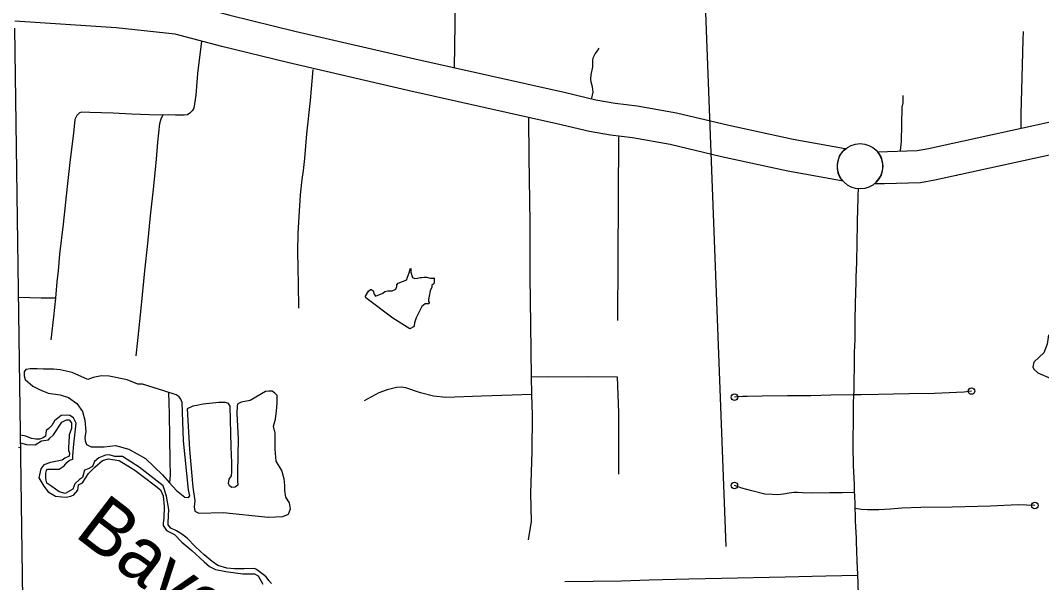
# Model space of a CAD drawing. Extents: x 1127717 to 1741049, y 2026793 to 2244711.
# Drawn here: x 1289221 to 1297097, y 2102398 to 2106736 of the extents above; entities that cross this region are included whole.
import ezdxf

# ---------------------------------------------------------------- set-up
doc = ezdxf.new("R2010")
doc.units = 0
for name, color, linetype in [('10', 7, 'Continuous'), ('2', 7, 'Continuous'), ('24', 7, 'Continuous'), ('31', 7, 'Continuous'), ('35', 7, 'Continuous'), ('5', 7, 'Continuous')]:
    doc.layers.add(name, color=color, linetype=linetype)

msp = doc.modelspace()

# ---------------------------------------------------------------- linework, layer by layer
at = {"layer": '10'}
for points in [[(1289179.3, 2106980.8), (1289979, 2106928.2), (1290461.1, 2106877.2), (1290836.1, 2106777), (1291337.3, 2106654.2)], [(1291279.5, 2106411), (1290774, 2106534.8), (1290415.4, 2106630.7), (1289960.3, 2106678.8), (1289177.8, 2106730.6)], [(1291337.3, 2106654.2), (1292263.9, 2106440), (1293413.8, 2106182.9), (1293659.5, 2106123.9), (1293808.1, 2106097.8), (1293978.4, 2106076.8), (1294281.4, 2106024.4), (1294684.5, 2105928.6), (1295180.4, 2105820.3), (1295582.2, 2105748.2)], [(1295558.2, 2105498.5), (1295552.6, 2105499.1), (1295140.4, 2105573.1), (1294628.9, 2105684.9), (1294231.2, 2105779.4), (1293941.8, 2105829.5), (1293771.2, 2105850.4), (1293608.6, 2105879), (1293357.3, 2105939.4), (1292208.5, 2106196.2), (1291279.5, 2106411)], [(1295830.9, 2105723.6), (1296135.9, 2105732.8), (1296223.9, 2105748.7), (1297326.3, 2105989.4), (1297777.1, 2106096.7), (1297925, 2106120.5), (1298884, 2106193.6), (1299004.5, 2106199.4), (1299783, 2106134), (1299881.1, 2106117.4), (1301117.7, 2105747.5)], [(1301415.4, 2105356.5), (1301034.6, 2105511.4), (1299824.2, 2105873.5), (1299751.6, 2105885.8), (1299000, 2105948.9), (1298901.1, 2105944.1), (1297954.4, 2105872), (1297825.9, 2105851.4), (1297381.9, 2105745.7), (1296272.8, 2105503.5), (1296162.1, 2105483.4), (1295884.9, 2105475.1), (1295807.6, 2105475.7)], [(1296442.2, 2105540.5), (1296413.7, 2105534.3)]]:
    msp.add_lwpolyline(points, dxfattribs=at)
for centre, radius, start, end in [((1295700.7, 2105610.8), 181.4, 130.79211, 218.24709), ((1295696.9, 2105611.2), 175, 309.25532, 39.99123)]:
    msp.add_arc(centre, radius, start, end, dxfattribs=at)
at = {"layer": '2'}
msp.add_lwpolyline([(1289248.7, 2101537.9), (1289178.5, 2106676.9)], dxfattribs=at)
at = {"layer": '24'}
msp.add_circle((1295696.9, 2105611.2), 175, dxfattribs=at)
at = {"layer": '31'}
for points in [[(1292567.4, 2106372.2), (1292578.5, 2107043.3), (1292584.3, 2107396.4), (1292585.4, 2107433.3)], [(1296939.3, 2105904.9), (1296939.3, 2106019.2), (1296946.9, 2106292.8), (1296954.5, 2106589.2), (1296957.5, 2106650)], [(1290616.7, 2106576.9), (1290587.1, 2106326.4), (1290574, 2106159.9), (1290557.7, 2106058.7), (1290546.3, 2106037.5), (1290528.4, 2106019.5), (1290508.8, 2106008.1), (1290482.7, 2106004.8), (1290415.8, 2106006.5), (1290362, 2106008.1), (1290317.9, 2106006.5), (1290215.1, 2106008.1), (1290078.1, 2106013), (1289936.1, 2106019.5), (1289756.7, 2106026.1), (1289694.7, 2106029.3), (1289676.7, 2106022.8), (1289655.5, 2106001.6), (1289640.9, 2105970.6), (1289629.4, 2105865.5), (1289603.3, 2105663.1), (1289580.5, 2105454.2), (1289549.5, 2105163.7), (1289521.8, 2104932), (1289512, 2104803.3), (1289502.2, 2104718.5), (1289490.8, 2104592.8)], [(1293627.7, 2106137.7), (1293638.6, 2106182.5), (1293633.9, 2106223.4), (1293622.5, 2106260.4), (1293619.6, 2106283.2), (1293623.4, 2106316.5), (1293634.8, 2106377.3), (1293634.8, 2106406.7), (1293634.8, 2106432.4), (1293640.5, 2106452.3), (1293652.9, 2106478), (1293670.9, 2106502.7), (1293684.2, 2106522.6)], [(1291475.6, 2106356.9), (1291454.5, 2106118.6), (1291426.8, 2105860.7), (1291410.5, 2105669.7), (1291400.7, 2105578.3), (1291390.9, 2105508.2), (1291379.5, 2105390.7), (1291368.1, 2105224.2), (1291361.5, 2105092), (1291358.3, 2104955.9), (1291361.5, 2104823.7), (1291363.2, 2104701.3), (1291364.8, 2104516.9)], [(1296009.2, 2105731.7), (1296016.7, 2105802.9), (1296020.5, 2106067), (1296028.1, 2106101.2), (1296028.1, 2106156.3)], [(1290112.8, 2104148.2), (1290126, 2104266), (1290155.1, 2104538.5), (1290181.5, 2104803.2), (1290202.7, 2105014.1), (1290223.9, 2105228.4), (1290250.3, 2105458.6), (1290270.1, 2105665.6), (1290279.4, 2105797.9), (1290296.6, 2105940.8), (1290305.9, 2105976.5), (1290317.9, 2106006.5)], [(1293140, 2102728.1), (1293163.3, 2102870.1), (1293158.4, 2103089.3), (1293166.6, 2103409.9), (1293169.9, 2103691.3), (1293165, 2103849.9), (1293163.3, 2103989), (1293158.4, 2104386.9), (1293151.9, 2104761.5), (1293153.5, 2105176.1), (1293145.6, 2105680), (1293140.8, 2105987.8)], [(1293834.7, 2105839.3), (1293825.6, 2104422)], [(1295679, 2102454), (1295678.5, 2102478.2), (1295677.2, 2102496.4), (1295676.2, 2102522.1), (1295675.3, 2102551.4), (1295674.3, 2102584), (1295672.7, 2102619.3), (1295671.1, 2102657.6), (1295669.9, 2102698.5), (1295668.1, 2102741.1), (1295666.8, 2102784.8), (1295664.3, 2102829.6), (1295662.4, 2102874.4), (1295660.6, 2102920.2), (1295658.9, 2102966.6), (1295657.9, 2103013.6), (1295656.3, 2103060.5), (1295654.6, 2103107.9), (1295652.5, 2103155.9), (1295650.6, 2103204.7), (1295648.6, 2103253.7), (1295646.8, 2103303.2), (1295645, 2103352.6), (1295643, 2103402), (1295642.5, 2103451.8), (1295642.7, 2103501.6), (1295643.5, 2103550.2), (1295644.7, 2103598.2), (1295645.8, 2103645.8), (1295645.3, 2103692.8), (1295646, 2103740.7), (1295647, 2103789), (1295648.6, 2103837.6), (1295650, 2103886.7), (1295650.9, 2103935.8), (1295652, 2103984.3), (1295653.4, 2104032.5), (1295654, 2104080.1), (1295654.3, 2104127.6), (1295654.9, 2104175.5), (1295656.1, 2104224), (1295658, 2104273.7), (1295657.9, 2104324), (1295658.7, 2104376.7), (1295660, 2104430.2), (1295664, 2104649.1), (1295665.4, 2104703.9), (1295667.1, 2104758.6), (1295668.6, 2104813), (1295670.5, 2104866.8), (1295672.3, 2104919.8), (1295673.1, 2104971.7), (1295674, 2105022.2), (1295674.7, 2105071.3), (1295675.6, 2105119.1), (1295676.4, 2105165), (1295677.4, 2105210.5), (1295678.4, 2105255.1), (1295679.5, 2105299.6), (1295681.3, 2105343.3), (1295682.7, 2105385.6), (1295684.4, 2105436.6)], [(1289490.8, 2104592.8), (1289379.8, 2104594.4), (1289206.9, 2104597.8)], [(1289490.8, 2104592.8), (1289475.3, 2104448.6), (1289455.4, 2104271.3)], [(1297151.2, 2104310.2), (1297140.5, 2104237.9), (1297113.5, 2104170.4), (1297077.4, 2104138.8), (1297036.9, 2104098.3), (1297027.9, 2104062.3), (1297036.9, 2104044.2), (1297068.4, 2104017.2), (1297163, 2103976.7), (1297203.5, 2103954.1), (1297208, 2103936.1), (1297208, 2103855), (1297199, 2103512.7)], [(1293163.3, 2103989), (1293292.5, 2103986.2), (1293596.7, 2103989.5), (1293824.2, 2103985.7)], [(1293824.2, 2103985.7), (1293834.4, 2103707.8), (1293834.4, 2103585.5), (1293834.4, 2103419), (1293832.7, 2103305.1), (1293834.4, 2103235.5)], [(1293165, 2103849.9), (1293014.5, 2103843.9), (1292775.8, 2103835.7), (1292501.1, 2103827.5), (1292406.3, 2103835.7), (1292306.5, 2103863.5), (1292193.7, 2103901.1), (1292156.1, 2103906), (1292120.1, 2103904.4), (1292048.2, 2103886.4), (1291984.4, 2103861.9), (1291871.6, 2103799.7)], [(1296556.2, 2103876.4), (1296497.3, 2103866.9), (1296271.3, 2103857.4), (1296073.8, 2103855.5), (1295836.4, 2103849.8), (1295705.3, 2103846), (1295648.8, 2103846)], [(1295648.8, 2103846), (1295472.3, 2103844.1), (1295316.5, 2103838.4), (1295138, 2103838.4), (1294940.5, 2103836.5), (1294824.6, 2103834.6), (1294790.4, 2103834.6), (1294727.8, 2103828.9)], [(1295655.1, 2103093.7), (1295558, 2103090.3), (1295459.9, 2103090.3), (1295322.5, 2103088.6), (1295252.2, 2103090.3), (1295213, 2103093.6), (1295185.2, 2103093.6), (1295150.8, 2103088.6), (1295105, 2103080.5), (1295059.3, 2103075.6), (1295020, 2103077.2), (1294962.8, 2103080.5), (1294863, 2103106.6), (1294784.6, 2103127.9), (1294727.3, 2103147.5)], [(1297044.3, 2102992.9), (1296917.1, 2102998.6), (1296702.4, 2102989.1), (1296408.1, 2102981.5), (1296164.9, 2102977.7), (1296018.7, 2102973.9), (1295931.3, 2102964.4), (1295840.2, 2102960.6), (1295754.7, 2102958.7), (1295707.2, 2102962.5), (1295658.8, 2102970.1)], [(1295679, 2102454), (1295432.1, 2102449.1), (1295119.8, 2102440.9), (1294627.6, 2102431.1), (1294375.8, 2102424.5), (1294070, 2102416.4), (1293857.4, 2102409.8), (1293418.4, 2102403.3)], [(1295958, 2101269.5), (1295927.5, 2101281.2), (1295898.4, 2101296.3), (1295872, 2101316.7), (1295848.5, 2101341.2), (1295827.5, 2101368.1), (1295807.8, 2101396.6), (1295788, 2101425.1), (1295768, 2101454.4), (1295748.6, 2101484.4), (1295730.7, 2101513.7), (1295707.5, 2101571.2), (1295704, 2101598.1), (1295704.4, 2101624.3), (1295695.3, 2101937.1), (1295690.4, 2102084.3), (1295685.5, 2102293.7), (1295682.2, 2102398.4), (1295679, 2102454)]]:
    msp.add_lwpolyline(points, dxfattribs=at)
for centre in [(1296556.2, 2103876.4), (1294727.8, 2103828.9), (1294727.3, 2103147.5), (1297044.3, 2102992.9)]:
    msp.add_circle(centre, 25, dxfattribs=at)
at = {"layer": '35'}
for points in [[(1291884.7, 2104595), (1291881.4, 2104608.1), (1291905.9, 2104647.4), (1291920.6, 2104660.4), (1291928.8, 2104660.4), (1291940.2, 2104650.6), (1291950.1, 2104624.5), (1291958.2, 2104609.7), (1291972.9, 2104613), (1292017.1, 2104631), (1292030.2, 2104645.7), (1292054.7, 2104649), (1292087.4, 2104649), (1292115.2, 2104662.1), (1292123.4, 2104683.3), (1292125, 2104696.4), (1292134.8, 2104707.9), (1292167.5, 2104721), (1292200.2, 2104734.1), (1292203.5, 2104747.1), (1292221.5, 2104796.2), (1292228, 2104819.1), (1292232.9, 2104822.4), (1292232.9, 2104794.6), (1292244.4, 2104753.7), (1292262.4, 2104745.5), (1292283.6, 2104747.1), (1292304.9, 2104753.7), (1292316.3, 2104753.7), (1292335.9, 2104755.3), (1292352.3, 2104755.3), (1292381.7, 2104748.8), (1292407.9, 2104748.8), (1292412.8, 2104750.4), (1292411.2, 2104729.1), (1292411.2, 2104712.8), (1292409.5, 2104703), (1292394.8, 2104693.2), (1292393.2, 2104678.4), (1292380.1, 2104650.6), (1292373.6, 2104609.7), (1292368.6, 2104583.6), (1292368.6, 2104567.2), (1292375.2, 2104554.1), (1292367, 2104549.2), (1292342.5, 2104549.2), (1292316.3, 2104529.6), (1292316.3, 2104527.9), (1292272.2, 2104441.3), (1292260.7, 2104403.6), (1292257.5, 2104380.7), (1292252.6, 2104372.6), (1292223.1, 2104356.2)], [(1292223.1, 2104356.2), (1292093.9, 2104439.6), (1291884.7, 2104595)], [(1290325.8, 2103877.4), (1290162.1, 2103930.3), (1290126.8, 2103930.3), (1290043.6, 2103963.1), (1289905.1, 2103990.8), (1289847.1, 2103993.3), (1289781.6, 2103980.7), (1289741.3, 2103965.6), (1289620.4, 2104018.5), (1289527.2, 2104041.2), (1289476.8, 2104046.2), (1289398.7, 2104046.2), (1289350.8, 2104048.8), (1289295.4, 2104048.8), (1289262.6, 2104043.7), (1289250, 2104023.6), (1289250, 2103993.3), (1289257.6, 2103965.6), (1289315.5, 2103915.2), (1289368.4, 2103887.5), (1289433.9, 2103859.7), (1289527.2, 2103847.1), (1289592.7, 2103827), (1289655.6, 2103781.6), (1289698.5, 2103718.6), (1289718.6, 2103650.5), (1289726.2, 2103564.9), (1289718.6, 2103514.5), (1289721.2, 2103491.8), (1289731.2, 2103464), (1289766.5, 2103446.4), (1289867.3, 2103446.4), (1289952.9, 2103456.5), (1290056.2, 2103428.8), (1290184.7, 2103355.7), (1290315.7, 2103229.7), (1290371.2, 2103169.2), (1290424.1, 2103108.7), (1290489.6, 2103058.3), (1290517.3, 2103055.8), (1290527.4, 2103068.4), (1290517.3, 2103113.7), (1290479.5, 2103491.8), (1290469.4, 2103789.2), (1290456.8, 2103814.4), (1290444.2, 2103832), (1290421.6, 2103847.1)], [(1290421.6, 2103847.1), (1290325.8, 2103877.4)], [(1290363.1, 2103865.6), (1290368.6, 2103701), (1290373.7, 2103335.5), (1290376.2, 2103227.1), (1290371.2, 2103169.2)], [(1290507.2, 2103738.8), (1290524.8, 2103426.2), (1290550, 2103133.9), (1290565.2, 2103030.5), (1290560.1, 2102982.7), (1290565.2, 2102949.9), (1290597.9, 2102934.8), (1290784.3, 2102939.8), (1291132, 2102902), (1291245.4, 2102909.6), (1291288.2, 2102927.2), (1291303.3, 2102967.5), (1291295.8, 2103012.9), (1291268.1, 2103058.3), (1291260.5, 2103108.7), (1291260.5, 2103146.5), (1291255.5, 2103199.4), (1291237.8, 2103262.4), (1291192.5, 2103335.5), (1291184.9, 2103428.8), (1291184.9, 2103552.3), (1291172.3, 2103605.2), (1291187.5, 2103660.6), (1291195, 2103723.6), (1291200.1, 2103784.1), (1291200.1, 2103809.3), (1291200.1, 2103842.1), (1291182.4, 2103859.7), (1291162.3, 2103874.9), (1291137.1, 2103874.9), (1291111.9, 2103872.3), (1290993.5, 2103804.3), (1290922.9, 2103791.7), (1290897.7, 2103779.1), (1290892.7, 2103761.4), (1290890.2, 2103703.5), (1290900.2, 2103506.9), (1290895.2, 2103244.8), (1290895.2, 2103184.3), (1290897.7, 2103149), (1290877.6, 2103133.9), (1290852.4, 2103131.4), (1290832.2, 2103144), (1290824.7, 2103164.1), (1290829.7, 2103196.9), (1290849.9, 2103222.1), (1290852.4, 2103252.3), (1290852.4, 2103322.9), (1290847.3, 2103446.4), (1290837.3, 2103758.9), (1290824.7, 2103781.6), (1290802, 2103789.2), (1290751.6, 2103789.2), (1290630.7, 2103774), (1290580.3, 2103764), (1290550, 2103758.9)], [(1290550, 2103758.9), (1290507.2, 2103738.8)], [(1291157.2, 2102390.4), (1291137.1, 2102415.6), (1291116.9, 2102443.3), (1291091.7, 2102461), (1291061.5, 2102483.6), (1291041.3, 2102498.8), (1291026.2, 2102506.3), (1290945.6, 2102503.8), (1290872.5, 2102503.8), (1290812.1, 2102508.8), (1290744, 2102531.5), (1290698.7, 2102561.8), (1290638.2, 2102612.2), (1290570.2, 2102675.2), (1290507.2, 2102740.7), (1290464.4, 2102771), (1290424.1, 2102798.7), (1290381.2, 2102818.8), (1290361.1, 2102844), (1290361.1, 2102861.7), (1290366.1, 2102962.5), (1290348.5, 2103065.8), (1290320.8, 2103144), (1290136.9, 2103290.1), (1290008.4, 2103370.8), (1289947.9, 2103370.8), (1289905.1, 2103383.4), (1289877.4, 2103380.9), (1289824.5, 2103360.7), (1289791.7, 2103333), (1289776.6, 2103295.2), (1289743.8, 2103277.5), (1289716.1, 2103264.9), (1289706, 2103237.2), (1289698.5, 2103209.5), (1289675.8, 2103194.4), (1289640.5, 2103161.6), (1289625.4, 2103118.8), (1289565, 2103086), (1289519.6, 2103098.6), (1289464.2, 2103138.9), (1289423.9, 2103166.6), (1289416.3, 2103201.9), (1289416.3, 2103242.3), (1289421.3, 2103262.4), (1289428.9, 2103272.5), (1289466.7, 2103272.5), (1289502, 2103272.5), (1289519.6, 2103272.5), (1289557.4, 2103300.2), (1289577.5, 2103325.4), (1289600.2, 2103343.1), (1289600.2, 2103343.1), (1289625.4, 2103350.6), (1289625.4, 2103378.4), (1289633, 2103466.6), (1289650.6, 2103627.9), (1289630.5, 2103670.7), (1289602.7, 2103688.4), (1289572.5, 2103690.9), (1289534.7, 2103688.4), (1289484.3, 2103645.5), (1289464.2, 2103610.2), (1289439, 2103587.5), (1289418.8, 2103572.4), (1289416.3, 2103549.7), (1289413.8, 2103527.1), (1289396.2, 2103514.5), (1289368.4, 2103504.4), (1289340.7, 2103504.4), (1289305.5, 2103509.4), (1289262.6, 2103527.1), (1289221.4, 2103537.1)], [(1289222.3, 2103476.7), (1289267.7, 2103464), (1289333.2, 2103461.5), (1289383.6, 2103491.8), (1289436.5, 2103499.3), (1289446.5, 2103511.9), (1289476.8, 2103539.7), (1289539.8, 2103635.4), (1289575, 2103655.6), (1289597.7, 2103653.1), (1289615.3, 2103630.4), (1289615.3, 2103587.5), (1289597.7, 2103539.7), (1289595.2, 2103474.1), (1289592.7, 2103448.9), (1289592.7, 2103421.2), (1289600.2, 2103396), (1289597.7, 2103373.3), (1289562.4, 2103358.2), (1289542.3, 2103343.1), (1289451.6, 2103325.4), (1289401.2, 2103307.8), (1289378.5, 2103277.5), (1289363.4, 2103207), (1289401.2, 2103141.4), (1289433.9, 2103098.6), (1289491.9, 2103065.8), (1289539.8, 2103060.8), (1289572.5, 2103058.3), (1289610.3, 2103065.8), (1289633, 2103075.9), (1289663.2, 2103111.2), (1289668.2, 2103151.5), (1289698.5, 2103169.2), (1289746.3, 2103239.7), (1289794.2, 2103290.1), (1289854.7, 2103340.5), (1289897.5, 2103353.1), (1289983.2, 2103340.5), (1290104.1, 2103264.9), (1290252.8, 2103154), (1290300.6, 2103113.7), (1290320.8, 2103068.4), (1290328.3, 2102985.2), (1290325.8, 2102894.5), (1290320.8, 2102856.6), (1290320.8, 2102839), (1290348.5, 2102801.2), (1290409, 2102768.4), (1290464.4, 2102710.5), (1290542.5, 2102644.9), (1290638.2, 2102559.2), (1290678.5, 2102521.4), (1290726.4, 2102498.8), (1290804.5, 2102483.6), (1290935.5, 2102466), (1291026.2, 2102466), (1291053.9, 2102450.9), (1291089.2, 2102385.3)], [(1289205.7, 2103443.3), (1289222.8, 2103437.2)]]:
    msp.add_lwpolyline(points, dxfattribs=at)
at = {"layer": '5'}
msp.add_lwpolyline([(1294664.2, 2102677.2), (1294502.5, 2106933.8)], dxfattribs=at)

# ---------------------------------------------------------------- texts
at = {"layer": '35'}
msp.add_text('Bayou', height=422.4, rotation=322.60364, dxfattribs=at).set_placement((1289629.1, 2102762.6))

doc.saveas('drawing.dxf')
